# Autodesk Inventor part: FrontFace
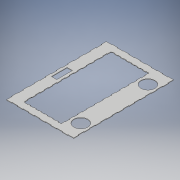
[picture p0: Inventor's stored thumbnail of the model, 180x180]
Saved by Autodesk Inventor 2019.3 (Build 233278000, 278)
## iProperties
Created: 2020-02
Part Number: FrontFace
Material: Generic
Document SubType Name: Modeling
Designer: KrystynWikoff
Density: 1 g/cm^3
Appearance: Default
Author: KrystynWikoff
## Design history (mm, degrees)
sketch "Sketch1"
  geometry: L1 (0, 0)-(304.8, 0); L2 (304.8, 0)-(304.8, -457.2); L3 (304.8, -457.2)-(0, -457.2); L4 (0, -457.2)-(0, 0); L5 (254, -31.75)-(84.582, -31.75); L6 (84.582, -31.75)-(84.582, -425.45); L7 (84.582, -425.45)-(254, -425.45); L8 (254, -425.45)-(254, -31.75)
  constraints: 16 end point, 4 parallel, 2 horizontal, 2 perpendicular
  dimensions: "d0" = 457.2 distance of L1.end L2.end; "d1" = 304.8 distance of L1.start L1.end; "d2" = 31.75 distance between parallel lines of L1 L5; "d3" = 31.75 distance between parallel lines of L3 L7; "d4" = 50.8 distance between parallel lines of L2 L8; "d5" = 84.582 distance between parallel lines of L4 L6
extrude "Extrusion1" new body sketch "Sketch1" distance "d6" = 2.3622; taper "d7" = 0 deg
sketch "Sketch2" dims "d16" = 25.4, "d26" = 25.4, "d35" = 25.4, "d44" = 25.4
  geometry: L1 (0, 0)-(0, 457.2) reference; L2 (0, 25.4)-(-2.362, 25.4); L3 (-2.362, 25.4)-(-2.362, 50.8); L4 (-2.362, 50.8)-(0, 50.8); L5 (0, 50.8)-(0, 25.4); L6 (-304.8, 0)-(0, 0) reference; L7 (0, 76.2)-(-2.362, 76.2); L8 (-2.362, 76.2)-(-2.362, 101.6); L9 (-2.362, 101.6)-(0, 101.6); L10 (0, 101.6)-(0, 76.2); L11 (0, 127)-(-2.362, 127); L12 (-2.362, 127)-(-2.362, 152.4); L13 (-2.362, 152.4)-(0, 152.4); L14 (0, 152.4)-(0, 127); L15 (0, 177.8)-(-2.362, 177.8); L16 (-2.362, 177.8)-(-2.362, 203.2); L17 (-2.362, 203.2)-(0, 203.2); L18 (0, 203.2)-(0, 177.8); L19 (0, 228.6)-(-2.362, 228.6); L20 (-2.362, 228.6)-(-2.362, 254); L21 (-2.362, 254)-(0, 254); L22 (0, 254)-(0, 228.6); L23 (0, 279.4)-(-2.362, 279.4); L24 (-2.362, 279.4)-(-2.362, 304.8); L25 (-2.362, 304.8)-(0, 304.8); L26 (0, 304.8)-(0, 279.4); L27 (0, 330.2)-(-2.362, 330.2); L28 (-2.362, 330.2)-(-2.362, 355.6); L29 (-2.362, 355.6)-(0, 355.6); L30 (0, 355.6)-(0, 330.2); L31 (0, 381)-(-2.362, 381); L32 (-2.362, 381)-(-2.362, 406.4); L33 (-2.362, 406.4)-(0, 406.4); L34 (0, 406.4)-(0, 381); L35 (0, 431.8)-(-2.362, 431.8); L36 (-2.362, 431.8)-(-2.362, 457.2); L37 (-2.362, 457.2)-(0, 457.2); L38 (0, 457.2)-(0, 431.8); L39 (0, 0)-(-25.4, 0); L40 (-25.4, 0)-(-25.4, 2.362); L41 (-25.4, 2.362)-(0, 2.362); L42 (0, 2.362)-(0, 0); L43 (-76.2, 2.362)-(-50.8, 2.362); L44 (-50.8, 2.362)-(-50.8, 0); L45 (-76.2, 0)-(-76.2, 2.362); L46 (-50.8, 0)-(-76.2, 0); L47 (-127, 2.362)-(-101.6, 2.362); L48 (-101.6, 2.362)-(-101.6, 0); L49 (-127, 0)-(-127, 2.362); L50 (-101.6, 0)-(-127, 0); L51 (-177.8, 2.362)-(-152.4, 2.362); L52 (-152.4, 2.362)-(-152.4, 0); L53 (-177.8, 0)-(-177.8, 2.362); L54 (-152.4, 0)-(-177.8, 0); L55 (-228.6, 2.362)-(-203.2, 2.362); L56 (-203.2, 2.362)-(-203.2, 0); L57 (-228.6, 0)-(-228.6, 2.362); L58 (-203.2, 0)-(-228.6, 0); L59 (-279.4, 2.362)-(-254, 2.362); L60 (-254, 2.362)-(-254, 0); L61 (-279.4, 0)-(-279.4, 2.362); L62 (-254, 0)-(-279.4, 0); L63 (-304.8, 0)-(-302.438, 0); L64 (-302.438, 0)-(-302.438, 25.4)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
  constraints: 240 end point, 8 parallel, 6 horizontal, 4 perpendicular, 2 point on line, 2 vertical, 1 collinear, 207 other
  dimensions: "d8" = 25.4 distance between parallel lines of L6 L2; "d9" = 25.4 distance of L2.end L3.end; "d10" = 2.3622 distance of L3.end L4.end; "d13" = 50.8 distance of L2.start L7.start; "d18" = 0 distance between parallel lines of L1 L42; "d19" = 25.4 distance of L40.end L41.end; "d20" = 2.3622 distance of L39.end L40.end; "d23" = 50.8 distance of L41.end L43.end; "d28" = 2.3622 distance of L64.end L65.end; "d29" = 25.4 distance of L63.end L64.end; "d32" = 50.8 distance of L63.end L67.start; "d37" = 25.4 distance of L101.end L102.end; "d38" = 2.3622 distance of L100.end L101.end; "d41" = 50.8 distance of L101.end L104.end
extrude "Extrusion2" cut sketch "Sketch2" distance "d46" = 2.9972; taper "d47" = 0 deg
sketch "Sketch3"
  geometry: L1 (-50.8, 0)-(-25.4, 0) reference; L2 (-84.582, 425.45)-(-84.582, 31.75) reference; L3 (-2.362, 76.2)-(-2.362, 101.6) reference; L4 (-2.362, 330.2)-(-2.362, 355.6) reference; L5 (-50.8, 457.2)-(-76.2, 457.2) reference; L6 (-292.1, 192.951)-(-267.589, 192.951); L7 (-267.589, 192.951)-(-267.589, 264.249); L8 (-267.589, 264.249)-(-292.1, 264.249); L9 (-292.1, 264.249)-(-292.1, 192.951); L10 (-302.438, 0)-(-279.4, 0) reference; L11 (-304.8, 254)-(-304.8, 228.6) reference; C1 r 31.75 at (-41.732, 76.2); C2 r 31.75 at (-41.732, 381); 1 further point
  constraints: 8 end point, 2 centre point, 2 parallel, 1 horizontal, 1 perpendicular
  dimensions: "d48" = 76.2 distance from line of C1.centre L1; "d50" = 63.5 diameter of C1; "d52" = 39.37 distance of L3.start C1.centre; "d53" = 63.5 diameter of C2; "d54" = 39.37 distance from line of L4 C2.centre; "d55" = 76.2 distance from line of L5 C2.centre; "d56" = 71.2978 distance of L8.end L6.start; "d57" = 24.511 distance of L7.end L8.end; "d58" = 192.9511 distance between parallel lines of L6 L10; "d59" = 12.7 distance between parallel lines of L11 L9
extrude "Extrusion3" cut sketch "Sketch3" distance "d60" = 2.9972; taper "d61" = 0 deg
sketch "Sketch4" dims "d71" = 25.4, "d81" = 25.4, "d91" = 25.4, "d100" = 25.4
  geometry: L1 (-84.582, 47.625)-(-82.22, 47.625); L2 (-82.22, 47.625)-(-82.22, 66.675); L3 (-82.22, 66.675)-(-84.582, 66.675); L4 (-84.582, 66.675)-(-84.582, 47.625); L5 (-84.582, 425.45)-(-84.582, 31.75) reference; L6 (-84.582, 31.75)-(-254, 31.75) reference; L7 (-84.582, 85.725)-(-82.22, 85.725); L8 (-82.22, 85.725)-(-82.22, 104.775); L9 (-82.22, 104.775)-(-84.582, 104.775); L10 (-84.582, 104.775)-(-84.582, 85.725); L11 (-84.582, 123.825)-(-82.22, 123.825); L12 (-82.22, 123.825)-(-82.22, 142.875); L13 (-82.22, 142.875)-(-84.582, 142.875); L14 (-84.582, 142.875)-(-84.582, 123.825); L15 (-84.582, 161.925)-(-82.22, 161.925); L16 (-82.22, 161.925)-(-82.22, 180.975); L17 (-82.22, 180.975)-(-84.582, 180.975); L18 (-84.582, 180.975)-(-84.582, 161.925); L19 (-84.582, 200.025)-(-82.22, 200.025); L20 (-82.22, 200.025)-(-82.22, 219.075); L21 (-82.22, 219.075)-(-84.582, 219.075); L22 (-84.582, 219.075)-(-84.582, 200.025); L23 (-84.582, 238.125)-(-82.22, 238.125); L24 (-82.22, 238.125)-(-82.22, 257.175); L25 (-82.22, 257.175)-(-84.582, 257.175); L26 (-84.582, 257.175)-(-84.582, 238.125); L27 (-84.582, 276.225)-(-82.22, 276.225); L28 (-82.22, 276.225)-(-82.22, 295.275); L29 (-82.22, 295.275)-(-84.582, 295.275); L30 (-84.582, 295.275)-(-84.582, 276.225); L31 (-84.582, 314.325)-(-82.22, 314.325); L32 (-82.22, 314.325)-(-82.22, 333.375); L33 (-82.22, 333.375)-(-84.582, 333.375); L34 (-84.582, 333.375)-(-84.582, 314.325); L35 (-84.582, 352.425)-(-82.22, 352.425); L36 (-82.22, 352.425)-(-82.22, 371.475); L37 (-82.22, 371.475)-(-84.582, 371.475); L38 (-84.582, 371.475)-(-84.582, 352.425); L39 (-84.582, 390.525)-(-82.22, 390.525); L40 (-82.22, 390.525)-(-82.22, 409.575); L41 (-82.22, 409.575)-(-84.582, 409.575); L42 (-84.582, 409.575)-(-84.582, 390.525); L43 (-254, 31.75)-(-254, 425.45) reference; L44 (-254, 47.625)-(-256.362, 47.625); L45 (-256.362, 47.625)-(-256.362, 66.675); L46 (-256.362, 66.675)-(-254, 66.675); L47 (-254, 66.675)-(-254, 47.625); L48 (-256.362, 104.775)-(-254, 104.775); L49 (-254, 104.775)-(-254, 85.725); L50 (-254, 85.725)-(-256.362, 85.725); L51 (-256.362, 85.725)-(-256.362, 104.775); L52 (-256.362, 142.875)-(-254, 142.875); L53 (-254, 142.875)-(-254, 123.825); L54 (-254, 123.825)-(-256.362, 123.825); L55 (-256.362, 123.825)-(-256.362, 142.875); L56 (-256.362, 180.975)-(-254, 180.975); L57 (-254, 180.975)-(-254, 161.925); L58 (-254, 161.925)-(-256.362, 161.925); L59 (-256.362, 161.925)-(-256.362, 180.975); L60 (-256.362, 219.075)-(-254, 219.075); L61 (-254, 219.075)-(-254, 200.025); L62 (-254, 200.025)-(-256.362, 200.025); L63 (-256.362, 200.025)-(-256.362, 219.075); L64 (-256.362, 257.175)-(-254, 257.175)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; 1 further point
  constraints: 272 end point, 8 parallel, 6 horizontal, 4 perpendicular, 2 point on line, 2 vertical, 1 collinear, 239 other
  dimensions: "d62" = 19.05 distance of L1.end L2.end; "d63" = 0 distance between parallel lines of L5 L4; "d64" = 15.875 distance between parallel lines of L6 L1; "d65" = 2.3622 distance of L1.start L1.end; "d68" = 38.1 distance of L1.start L7.start; "d73" = 15.875 distance from line of L6.end L44; "d74" = 19.05 distance of L44.end L45.end; "d75" = 2.3622 distance of L44.start L44.end; "d78" = 38.1 distance of L45.end L48.start; "d83" = 2.3622 distance of L84.end L85.end; "d84" = 12.7 distance of L85.end L86.end; "d85" = 0 distance between parallel lines of L5 L87; "d88" = 25.4 distance of L84.end L88.end; "d93" = 12.7 distance of L113.end L114.end; "d94" = 2.3622 distance of L112.end L113.end; "d97" = 25.4 distance of L112.end L116.end
extrude "Extrusion4" cut sketch "Sketch4" distance "d102" = 2.9972; taper "d103" = 0 deg
body "Solid1"
